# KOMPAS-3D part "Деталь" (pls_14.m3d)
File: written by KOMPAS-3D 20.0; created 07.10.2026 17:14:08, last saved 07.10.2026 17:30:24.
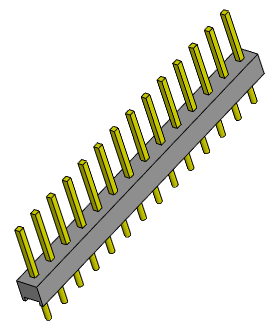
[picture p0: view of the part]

Document properties: Полное имя файла: D:\myProjects\Progect_esp32\box_compas\pls_14.m3d

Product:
- Part/product: Деталь
    Масса: 0.00182492

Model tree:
1. Эскиз:1
2. Элемент выдавливания:1
     Расстояние 1 = 2.5
3. Эскиз:2  (with: Элемент выдавливания:1)
4. Элемент выдавливания:2
     Расстояние 1 = 6
5. Массив по сетке:1  (with: Элемент выдавливания:2, Эскиз:2)  (14 pattern instances)
     Шаг 1 = 2.54; Угол раствора = 90
6. Эскиз:3  (with: Элемент выдавливания:1)
7. Элемент выдавливания:3
     Расстояние 1 = 3
8. Массив по сетке:2  (with: Элемент выдавливания:3, Эскиз:3)  (14 pattern instances)
     Шаг 1 = 2.54; Угол раствора = 90; Геометрический массив = 128
9. Эскиз:4  (with: Элемент выдавливания:1)
10. Элемент выдавливания:4
     Расстояние 2 = 35.56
